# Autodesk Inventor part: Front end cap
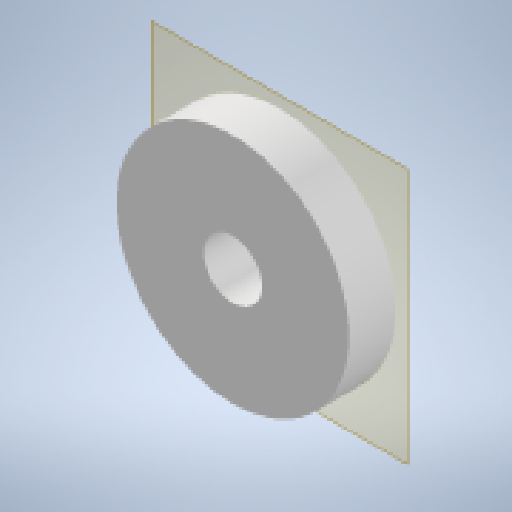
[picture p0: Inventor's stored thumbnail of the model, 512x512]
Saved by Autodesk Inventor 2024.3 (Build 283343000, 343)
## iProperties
Created: 2024-12
Part Number: Front end cap
Material: Generic
Document SubType Name: Modeling
Designer: ruhr
Density: 1 g/cm^3
Appearance: Default
Author: ruhr
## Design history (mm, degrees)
workplane "Work Plane1"
sketch "Sketch1"
  geometry: C1 r 5 at (0, 0) reference; C2 r 22.5 at (0, 0) reference; 1 further point
extrude "Extrusion2" new body sketch "Sketch1" distance "d2" = 8; taper "d3" = 0 deg
body "Solid2"
node "Reference2"
node "Reference3"
